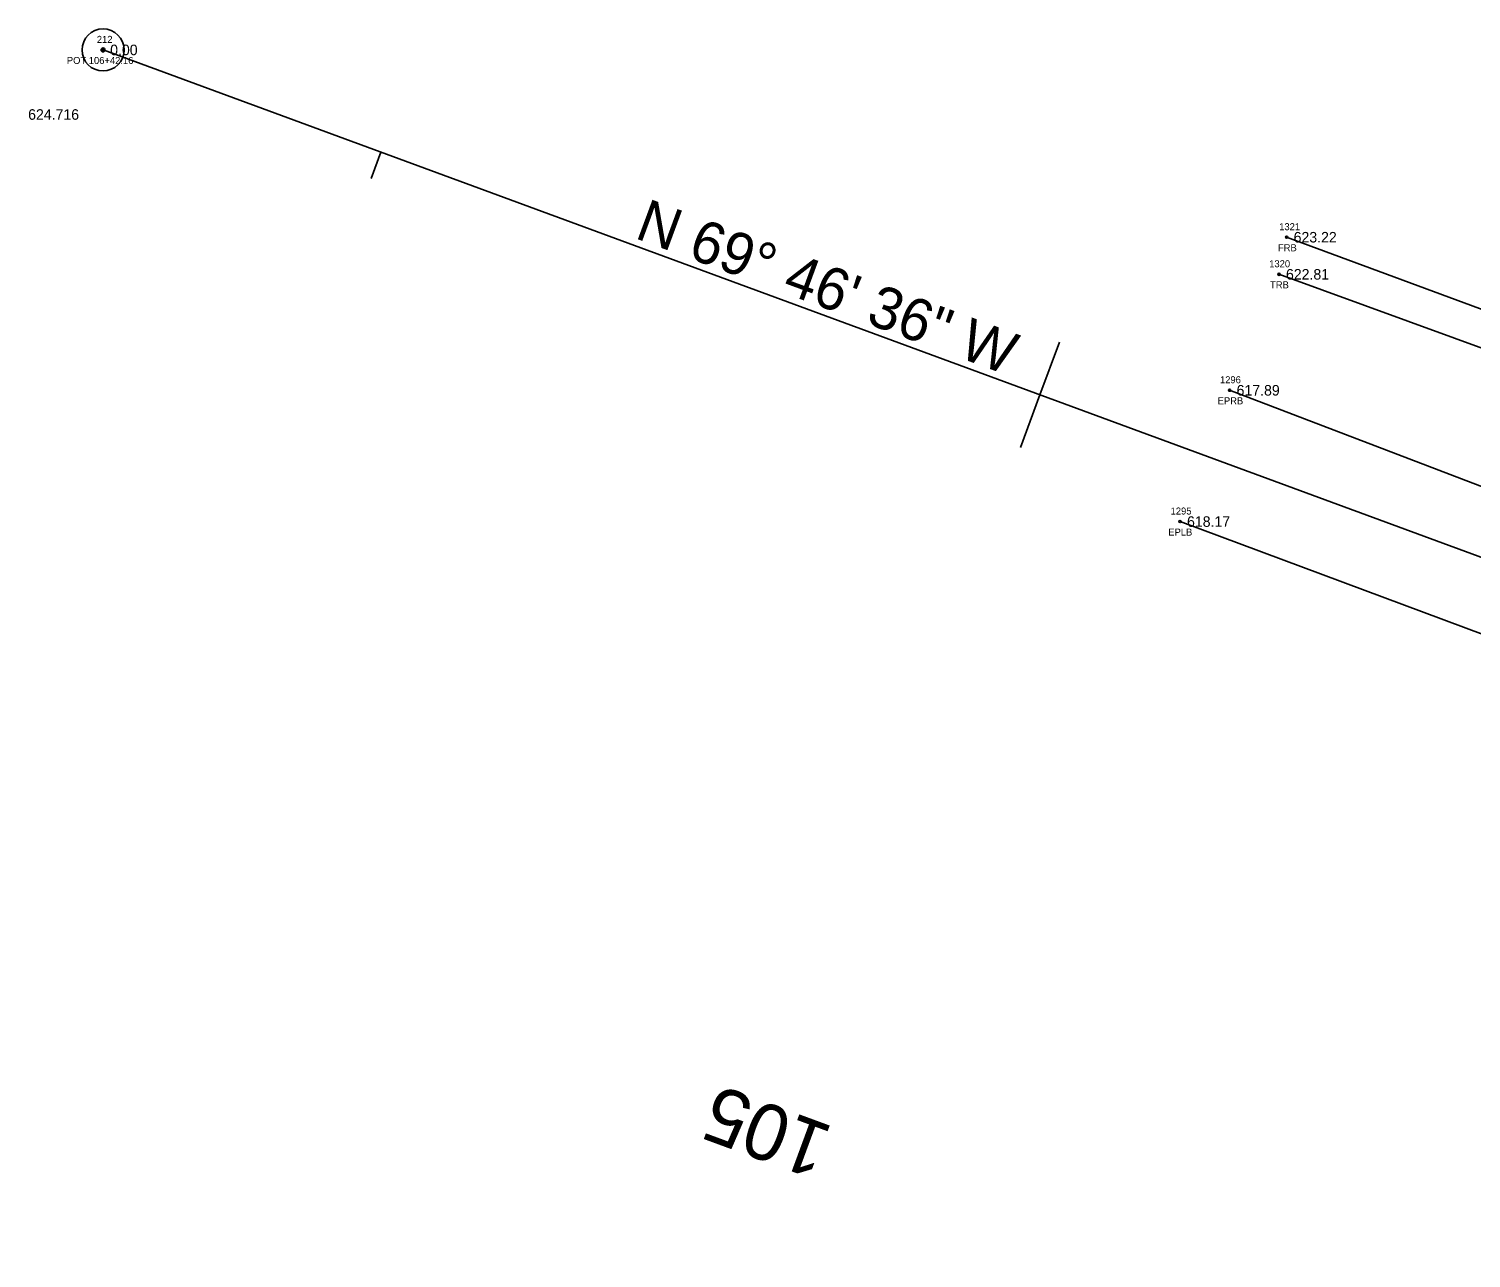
# Model space of a CAD drawing. Extents: x 1529475 to 1532053, y 876698 to 877911.
# Drawn here: x 1530021.3 to 1530226.7, y 877259 to 877434.2 of the extents above; entities that cross this region are included whole.
import ezdxf

# ---------------------------------------------------------------- set-up
doc = ezdxf.new("R2010")
doc.units = 0
for name, color, linetype in [('RD_EX_Fence_Other', 7, 'Continuous'), ('RD_EX_Fence_Other_txCode', 7, 'Continuous'), ('RD_EX_Road', 7, 'Continuous'), ('RD_EX_Road_txCode', 7, 'Continuous'), ('RD_EX_TX_Fence_Other_ELEV', 7, 'Continuous'), ('RD_EX_TX_Road_ELEV', 7, 'Continuous'), ('RD_EX_TX_VEG_ELEV', 7, 'Continuous'), ('RD_EX_VEG', 7, 'Continuous'), ('RD_EX_VEG_txCode', 7, 'Continuous'), ('RD_HC_Cl', 7, 'Continuous'), ('RD_HC_Data', 7, 'Continuous'), ('RD_HC_Data_Tic', 7, 'Continuous'), ('RD_HC_Survey_ELEV', 7, 'Continuous'), ('RD_HC_TX_Sta50', 7, 'Continuous'), ('RD_HC_txCode', 7, 'Continuous'), ('RD_SMD_Locator', 7, 'Continuous')]:
    doc.layers.add(name, color=color, linetype=linetype)

msp = doc.modelspace()

# ---------------------------------------------------------------- linework, layer by layer
at = {"layer": 'RD_EX_Fence_Other'}
msp.add_lwpolyline([(1530278.51, 877394.46), (1530270.66, 877378.5), (1530200.44, 877404.47)], dxfattribs=at)
at = {"layer": 'RD_EX_Road'}
for points in [[(1530865.35, 877283.66), (1530865.36, 877280.61), (1530815.01, 877277.89), (1530763.54, 877277.33), (1530711.24, 877277.01), (1530660.64, 877277.93), (1530609.51, 877281.74), (1530559.88, 877286.96), (1530511.03, 877294.4), (1530460.35, 877303.35), (1530410.49, 877314.53), (1530361.04, 877326.77), (1530310.59, 877340.83), (1530305.81, 877342.41), (1530288.71, 877347.95), (1530253.55, 877359.27), (1530192.32, 877382.67)], [(1530866.41, 877261.44), (1530852.87, 877260.97), (1530806.23, 877259.4), (1530762.44, 877259.05), (1530711.8, 877259.77), (1530659.89, 877260.87), (1530608.32, 877263.5), (1530557.85, 877268.33), (1530507.29, 877275.71), (1530456.72, 877284.51), (1530406.3, 877294.52), (1530356.75, 877305.76), (1530307.05, 877320.51), (1530246, 877341.34), (1530185.26, 877363.97)]]:
    msp.add_lwpolyline(points, dxfattribs=at)
at = {"layer": 'RD_EX_VEG'}
msp.add_lwpolyline([(1530284.48, 877398.76), (1530287.5, 877363.24), (1530279.98, 877369.84), (1530199.35, 877399.19)], dxfattribs=at)
at = {"layer": 'RD_HC_Cl'}
msp.add_line((1530237.3, 877355.49), (1530031.91, 877431.15), dxfattribs=at)
at = {"layer": 'RD_HC_Data'}
for radius in [3, 0.282]:
    msp.add_circle((1530031.91, 877431.15), radius, dxfattribs=at)
at = {"layer": 'RD_HC_Data_Tic'}
for p, q in [((1530071.47, 877416.58), (1530070.09, 877412.83)), ((1530165.31, 877382.01), (1530168.08, 877389.52)), ((1530165.31, 877382.01), (1530162.54, 877374.5))]:
    msp.add_line(p, q, dxfattribs=at)
at = {"layer": 'RD_SMD_Locator'}
for centre in [(1530031.91, 877431.15), (1530200.44, 877404.47), (1530199.35, 877399.19), (1530192.32, 877382.67), (1530185.26, 877363.97)]:
    msp.add_circle(centre, 0.15, dxfattribs=at)

# ---------------------------------------------------------------- texts
at = {"layer": 'RD_EX_Fence_Other_txCode'}
for s, p in [('1321', (1530199.38, 877405.47)), ('FRB', (1530199.21, 877402.47))]:
    msp.add_text(s, height=1, dxfattribs=at).set_placement(p)
at = {"layer": 'RD_EX_Road_txCode'}
for s, p in [('1296', (1530190.95, 877383.67)), ('EPRB', (1530190.62, 877380.67)), ('1295', (1530183.92, 877364.97)), ('EPLB', (1530183.59, 877361.97))]:
    msp.add_text(s, height=1, dxfattribs=at).set_placement(p)
at = {"layer": 'RD_EX_TX_Fence_Other_ELEV'}
msp.add_text('623.22', height=1.5, dxfattribs=at).set_placement((1530201.44, 877403.72))
at = {"layer": 'RD_EX_TX_Road_ELEV'}
for s, p in [('617.89', (1530193.32, 877381.92)), ('618.17', (1530186.26, 877363.22))]:
    msp.add_text(s, height=1.5, dxfattribs=at).set_placement(p)
at = {"layer": 'RD_EX_TX_VEG_ELEV'}
msp.add_text('622.81', height=1.5, dxfattribs=at).set_placement((1530200.35, 877398.44))
at = {"layer": 'RD_EX_VEG_txCode'}
for s, p in [('1320', (1530197.96, 877400.19)), ('TRB', (1530198.08, 877397.19))]:
    msp.add_text(s, height=1, dxfattribs=at).set_placement(p)
at = {"layer": 'RD_HC_Data'}
msp.add_text('N 69%%d 46\' 36" W', height=6, rotation=339.7768, dxfattribs=at).set_placement((1530107.44, 877404.4))
at = {"layer": 'RD_HC_Survey_ELEV'}
for s, p in [('0.00', (1530032.92, 877430.4)), ('624.716', (1530021.24, 877421.2))]:
    msp.add_text(s, height=1.5, dxfattribs=at).set_placement(p)
at = {"layer": 'RD_HC_TX_Sta50'}
msp.add_text('105', height=8, rotation=159.7768, dxfattribs=at).set_placement((1530136.14, 877277.66))
at = {"layer": 'RD_HC_txCode'}
for s, p in [('212', (1530031.02, 877432.15)), ('POT 106+42.16', (1530026.75, 877429.15))]:
    msp.add_text(s, height=1, dxfattribs=at).set_placement(p)

doc.saveas('drawing.dxf')
